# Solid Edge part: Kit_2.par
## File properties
Last saved by: ahadarics
Revision: 76
Dokumentum tartalom típus: 0
Sűrűség: 0,000 kg/m^3
Pontosság: 0,990
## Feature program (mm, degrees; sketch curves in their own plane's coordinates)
base feature "unnamed BaseFeature 1"
sketch for "Furat_1" plane through (0, 3.75, 13.5) normal (0, 0, 1) x-axis (0, 1, 0)
  hole centre (-0.25, 0) bore radius 4.283
hole "Furat_1" nominal diameter 9.728 finite  ThreadDepth = 7.5 mm
chamfer "Letörés_1" setback 0.7
sketch for "unnamed Protrusion 1" #1 plane through (0, 33.5, 0) normal (0, 1, 0) x-axis (0, 0, -1)
  line (-7.5498, -8) -> (7.5498, -8)
  arc centre (0, 0) radius 11 from (7.5498, -8) to (-7.5498, -8) cw
sketch for "unnamed Protrusion 1" #2 plane through (0, 33.5, 0) normal (0, 1, 0) x-axis (0, 0, -1)
  line (-7.5498, 8) -> (7.5498, 8)
extrude "unnamed Protrusion 1" add to key point along -normal
thread "unnamed Thread 1"
chamfer "Letörés_2" setback 1.5
sketch for "Kivágás_1" #1 plane through (0, 33.5, 0) normal (0, 1, 0) x-axis (0, 0, -1)
  line (-7.5498, -8) -> (7.5498, -8)
  arc centre (0, 0) radius 11 from (7.5498, -8) to (-7.5498, -8) cw
sketch for "Kivágás_1" #2 plane through (0, 33.5, 0) normal (0, 1, 0) x-axis (0, 0, -1)
  line (-7.5498, 8) -> (7.5498, 8)
extrude "Kivágás_1" cut finite 20 along -normal
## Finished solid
Body 1: solid body, 32 faces, 72 edges, 41 vertices.
  Faces by surface: plane 13, cylinder 11, cone 8
  Edges by curve: line 33, circle 31, intersection 4, spline 4
Bounding box of the edges (mm): 30.000 x 39.500 x 28.500, from (-15, -6, -15) to (15, 33.5, 13.5).
Cylindrical faces by radius (mm): R4 x1, R4.28 x1, R4.283 x1, R9.85 x2, R11 x4, R13.5 x1, R15 x1
Conical faces (half-angle, radius in mm at the cone's reference point): 45 deg R4.1 x2, 45 deg R4.983 x1, 45 deg R11 x2, 59 deg R2.1415 x1, 60 deg R10.425 x2
Planar faces by outward normal: +x 1, +y 7, +z 2, -x 1, -y 2
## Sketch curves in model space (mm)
arc centre (0, 33.5, 0) radius 11 from (8, 33.5, -7.5498) through (11, 33.5, 0) to (8, 33.5, 7.5498)
line (8, 33.5, 7.5498) -> (8, 33.5, -7.5498)
arc centre (0, 33.5, 0) radius 11 from (-8, 33.5, 7.5498) through (-11, 33.5, 0) to (-8, 33.5, -7.5498)
line (-8, 33.5, 7.5498) -> (-8, 33.5, -7.5498)
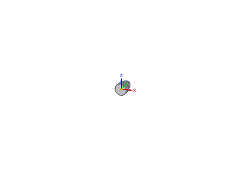
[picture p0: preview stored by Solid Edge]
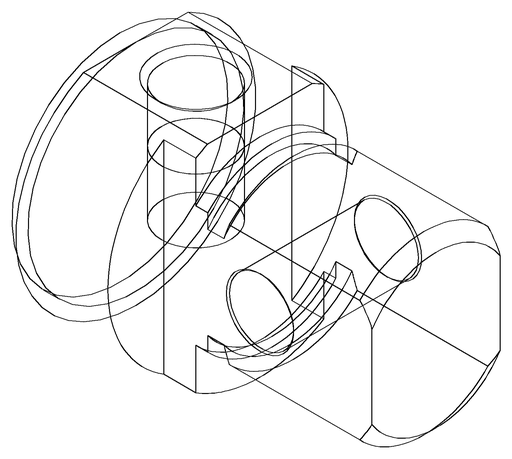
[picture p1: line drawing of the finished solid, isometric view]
